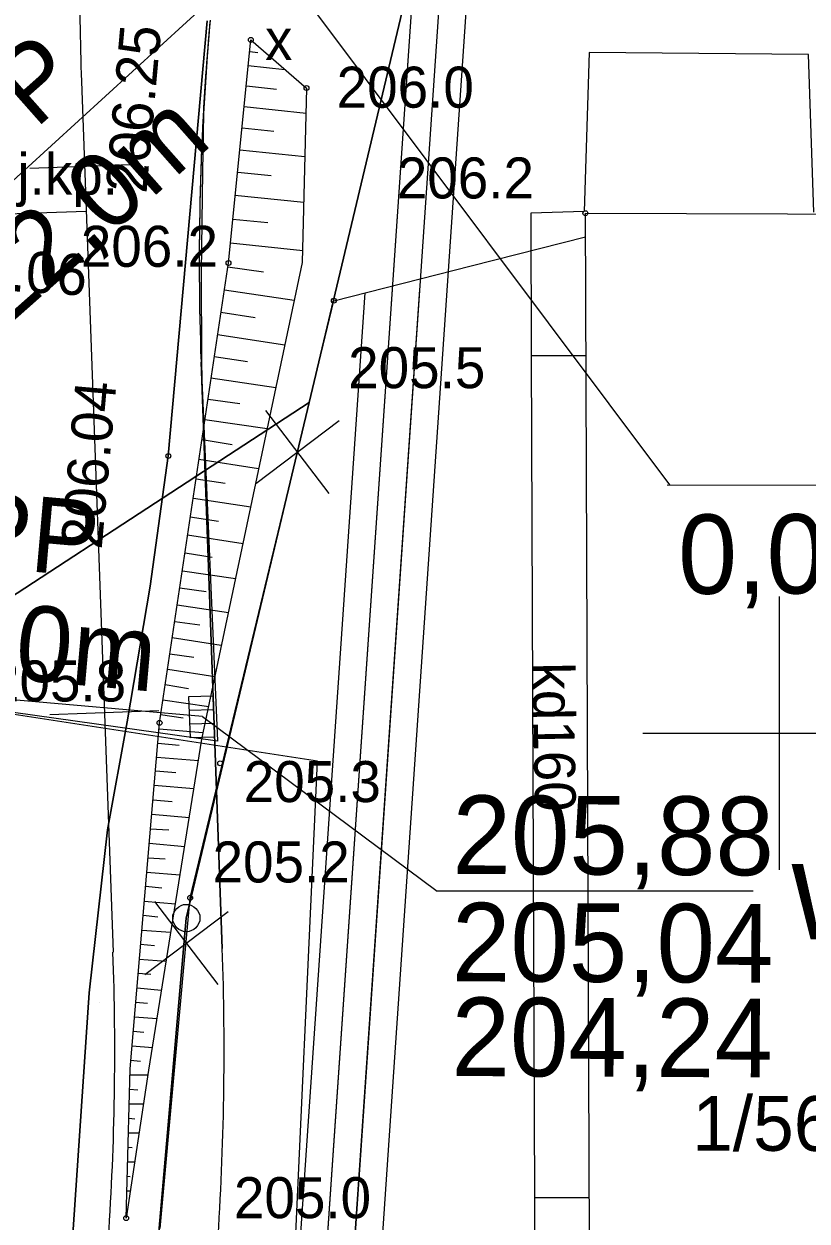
# Model space of a CAD drawing. Extents: x 6512606 to 6513347, y 6022524 to 6022728.
# Drawn here: x 6512736.18 to 6512750.51, y 6022641.08 to 6022662.97 of the extents above; entities that cross this region are included whole.
import ezdxf

# ---------------------------------------------------------------- set-up
doc = ezdxf.new("R2010")
doc.units = 0
for name, color, linetype in [('000 Inne (niezydentyfikowane)', 7, 'Continuous'), ('20', 7, 'Continuous'), ('202-punkt graniczny', 7, 'Continuous'), ('211-numer działki ewidencyjnej', 7, 'Continuous'), ('218-kontur użytku gruntowego', 7, 'Continuous'), ('219-działka ewidencyjna', 7, 'Continuous'), ('312-budynek ewidencyjny', 7, 'Continuous'), ('4', 7, 'Continuous'), ('Default', 7, 'Continuous'), ('jezdnia (powierzchnia)', 7, 'Continuous'), ('jezdnia (powierzchnia)-Atr17', 7, 'Continuous'), ('kolor_kostka_bet', 7, 'Continuous'), ('krawężnik (linia)', 7, 'Continuous'), ('Level 47', 7, 'Continuous'), ('Level 60', 7, 'Continuous'), ('maxp_kan_deszczowa', 7, 'Continuous'), ('maxp_kratki', 7, 'Continuous'), ('maxp_krawężnik', 7, 'Continuous'), ('maxp_likwidacje', 7, 'Continuous'), ('maxp_opisy', 7, 'Continuous'), ('maxp_os', 7, 'Continuous'), ('maxp_ramka_2', 7, 'Continuous'), ('ogrodzenie', 7, 'Continuous'), ('ogrodzenie trwałe (linia)', 7, 'Continuous'), ('pikieta naturalna', 7, 'Continuous'), ('pikieta naturalna-Atr2', 7, 'Continuous'), ('przewód kanalizacyjny (linia)', 7, 'Continuous'), ('przewód kanalizacyjny (linia)-Atr1', 7, 'Continuous'), ('punkt wysokościowy naturalny', 7, 'Continuous'), ('punkt wysokościowy naturalny-Atr2', 7, 'Continuous'), ('punkt wysokościowy sztuczny', 7, 'Continuous'), ('punkt wysokościowy sztuczny-Atr2', 7, 'Continuous'), ('skarpa nieumocniona', 7, 'Continuous'), ('właz okrągły - siec niezidentyfikowana (punkt)-Atr17', 7, 'Continuous')]:
    doc.layers.add(name, color=color, linetype=linetype)

# ---------------------------------------------------------------- blocks, each defined once
blk = doc.blocks.new('202')
at = {"layer": 'Default'}
blk.add_circle((0, 0), 2.5, dxfattribs=at)
blk = doc.blocks.new('PW01')
at = {"layer": 'Default'}
blk.add_circle((0, 0), 0.45, dxfattribs=at)
blk = doc.blocks.new('PW02')
at = {"layer": 'Default'}
blk.add_circle((0, 0), 0.45, dxfattribs=at)

msp = doc.modelspace()

# ---------------------------------------------------------------- linework, layer by layer
msp.add_line((6512740.034, 6022615.911), (6512743.337, 6022664.192))
msp.add_arc((6512787.452, 6022641.666), 50, 176.0863, 176.0865)
msp.add_arc((6512787.452, 6022641.666), 50, 176.0863, 176.0865)
at = {"layer": '000 Inne (niezydentyfikowane)'}
for points in [[(6512740.31, 6022662.47), (6512740.46, 6022662.45)], [(6512740.28, 6022662.21), (6512740.95, 6022662.14)], [(6512740.25, 6022661.84), (6512740.8, 6022661.78)], [(6512740.21, 6022661.46), (6512741.34, 6022661.34)], [(6512740.17, 6022661.07), (6512740.75, 6022661.01)], [(6512740.13, 6022660.67), (6512741.32, 6022660.55)], [(6512740.09, 6022660.26), (6512740.7, 6022660.2)], [(6512740.04, 6022659.84), (6512741.3, 6022659.71)], [(6512740, 6022659.4), (6512740.64, 6022659.34)], [(6512739.96, 6022658.97), (6512741.28, 6022658.83)], [(6512739.91, 6022658.53), (6512740.56, 6022658.44)], [(6512739.85, 6022658.11), (6512741.12, 6022657.92)], [(6512739.78, 6022657.7), (6512740.41, 6022657.6)], [(6512739.72, 6022657.29), (6512740.95, 6022657.1)], [(6512739.66, 6022656.89), (6512740.27, 6022656.8)], [(6512739.6, 6022656.5), (6512740.79, 6022656.32)], [(6512739.55, 6022656.11), (6512740.13, 6022656.03)], [(6512739.49, 6022655.74), (6512740.63, 6022655.57)], [(6512739.44, 6022655.37), (6512739.99, 6022655.28)], [(6512739.38, 6022655.01), (6512740.47, 6022654.84)], [(6512739.33, 6022654.65), (6512739.86, 6022654.57)], [(6512739.28, 6022654.3), (6512740.33, 6022654.14)], [(6512739.22, 6022653.96), (6512739.74, 6022653.88)], [(6512739.17, 6022653.63), (6512740.19, 6022653.47)], [(6512739.13, 6022653.3), (6512739.62, 6022653.22)], [(6512739.08, 6022652.97), (6512740.05, 6022652.83)], [(6512739.03, 6022652.66), (6512739.51, 6022652.59)], [(6512738.98, 6022652.35), (6512739.92, 6022652.21)], [(6512738.94, 6022652.04), (6512739.4, 6022651.98)], [(6512738.89, 6022651.75), (6512739.79, 6022651.61)], [(6512738.85, 6022651.45), (6512739.29, 6022651.39)], [(6512738.81, 6022651.17), (6512739.67, 6022651.04)], [(6512738.76, 6022650.89), (6512739.19, 6022650.82)], [(6512738.72, 6022650.61), (6512739.56, 6022650.49)], [(6512738.68, 6022650.34), (6512739.09, 6022650.28)], [(6512738.65, 6022650.08), (6512739.45, 6022650.01)], [(6512738.63, 6022649.82), (6512739.02, 6022649.78)], [(6512738.61, 6022649.56), (6512739.37, 6022649.5)], [(6512738.59, 6022649.31), (6512738.96, 6022649.28)], [(6512738.56, 6022649.05), (6512739.29, 6022648.99)], [(6512738.54, 6022648.78), (6512738.89, 6022648.75)], [(6512738.52, 6022648.52), (6512739.2, 6022648.46)], [(6512738.49, 6022648.25), (6512738.83, 6022648.23)], [(6512738.47, 6022647.99), (6512739.12, 6022647.93)], [(6512738.45, 6022647.72), (6512738.76, 6022647.7)], [(6512738.43, 6022647.46), (6512739.03, 6022647.41)], [(6512738.4, 6022647.2), (6512738.7, 6022647.17)], [(6512738.38, 6022646.93), (6512738.95, 6022646.88)], [(6512738.36, 6022646.67), (6512738.63, 6022646.64)], [(6512738.34, 6022646.4), (6512738.86, 6022646.36)], [(6512738.31, 6022646.14), (6512738.57, 6022646.12)], [(6512738.29, 6022645.87), (6512738.78, 6022645.83)], [(6512738.27, 6022645.61), (6512738.5, 6022645.59)], [(6512738.25, 6022645.34), (6512738.69, 6022645.3)], [(6512738.22, 6022645.08), (6512738.44, 6022645.06)], [(6512738.2, 6022644.81), (6512738.61, 6022644.78)], [(6512738.18, 6022644.55), (6512738.37, 6022644.53)], [(6512738.16, 6022644.28), (6512738.53, 6022644.25)], [(6512738.13, 6022644.02), (6512738.31, 6022644)], [(6512738.12, 6022643.75), (6512738.45, 6022643.75)], [(6512738.11, 6022643.49), (6512738.26, 6022643.48)], [(6512738.1, 6022643.22), (6512738.37, 6022643.22)], [(6512738.1, 6022642.96), (6512738.21, 6022642.95)], [(6512738.09, 6022642.69), (6512738.29, 6022642.69)], [(6512738.08, 6022642.43), (6512738.16, 6022642.42)], [(6512738.08, 6022642.16), (6512738.21, 6022642.16)], [(6512738.07, 6022641.9), (6512738.12, 6022641.89)], [(6512738.06, 6022641.63), (6512738.13, 6022641.63)]]:
    msp.add_lwpolyline(points, dxfattribs=at)
at = {"layer": '20'}
for p in [(6512739.443, 6022650.303), (6512749.517, 6022647.111)]:
    msp.add_line(p, (6512743.737, 6022647.111), dxfattribs=at)
at = {"layer": '218-kontur użytku gruntowego'}
for points in [[(6512745.51, 6022673.33), (6512741.4, 6022656.05)], [(6512741.4, 6022656.05), (6512745.51, 6022673.33)], [(6512741.4, 6022656.05), (6512733.08, 6022650.62)], [(6512733.08, 6022650.62), (6512741.4, 6022656.05)], [(6512741.4, 6022656.05), (6512739.15, 6022646.62)], [(6512739.15, 6022646.62), (6512741.4, 6022656.05)], [(6512739.15, 6022646.62), (6512737.73, 6022630.38)], [(6512737.73, 6022630.38), (6512739.15, 6022646.62)]]:
    msp.add_lwpolyline(points, dxfattribs=at)
at = {"layer": '219-działka ewidencyjna'}
for points in [[(6512745.51, 6022673.33), (6512739.15, 6022646.62)], [(6512739.15, 6022646.62), (6512735.75, 6022607.64)]]:
    msp.add_lwpolyline(points, dxfattribs=at)
at = {"layer": '312-budynek ewidencyjny'}
for points in [[(6512746.45, 6022659.51), (6512759.38, 6022659.47)], [(6512746.53, 6022639.13), (6512746.45, 6022659.51)]]:
    msp.add_lwpolyline(points, dxfattribs=at)
at = {"layer": '4'}
for points in [[(6512745.51, 6022673.33), (6512739.15, 6022646.62)], [(6512739.15, 6022646.62), (6512735.75, 6022607.64)]]:
    msp.add_lwpolyline(points, dxfattribs=at)
at = {"layer": 'Default'}
for p, q in [((6512750, 6022647.5), (6512750, 6022652.5)), ((6512747.5, 6022650), (6512752.5, 6022650))]:
    msp.add_line(p, q, dxfattribs=at)
at = {"layer": 'jezdnia (powierzchnia)'}
msp.add_lwpolyline([(6512736.3, 6022629.38), (6512737.37, 6022645.25), (6512737.71, 6022648.23), (6512738.07, 6022650.21), (6512738.49, 6022652.69), (6512738.82, 6022655.07), (6512739.53, 6022663.03)], dxfattribs=at)
at = {"layer": 'kolor_kostka_bet'}
for p, q in [((6512740.868, 6022628.114), (6512743.337, 6022664.192)), ((6512739.807, 6022646.065), (6512739.419, 6022656.788)), ((6512739.419, 6022656.788), (6512739.807, 6022646.065))]:
    msp.add_line(p, q, dxfattribs=at)
for centre, radius, start, end in [((6512789.386, 6022658.599), 50, 174.9005, 182.076), ((6512789.386, 6022658.599), 50, 174.9607, 182.076), ((6512687.841, 6022644.182), 52, 356.0865, 2.076), ((6512687.841, 6022644.182), 52, 356.0868, 2.076)]:
    msp.add_arc(centre, radius, start, end, dxfattribs=at)
at = {"layer": 'krawężnik (linia)'}
msp.add_lwpolyline([(6512739.53, 6022663.03), (6512738.82, 6022655.07), (6512738.49, 6022652.69), (6512738.07, 6022650.21), (6512737.71, 6022648.23), (6512737.37, 6022645.25), (6512736.3, 6022629.38)], dxfattribs=at)
at = {"layer": 'Level 60'}
for points in [[(6512738.287, 6022660.401), (6512736.288, 6022660.329)], [(6512738.649, 6022650.408), (6512736.651, 6022650.336)]]:
    msp.add_lwpolyline(points, dxfattribs=at)
at = {"layer": 'maxp_kan_deszczowa'}
for p, q in [((6512742.335, 6022665.911), (6512733.933, 6022658.237)), ((6512739.443, 6022650.303), (6512726.489, 6022651.44))]:
    msp.add_line(p, q, dxfattribs=at)
for points in [[(6512739.581, 6022663.017), (6512739.565, 6022662.833), (6512739.529, 6022662.375), (6512739.461, 6022661.334), (6512739.447, 6022660.268), (6512739.419, 6022658.432), (6512739.425, 6022656.82), (6512739.431, 6022656.459), (6512739.721, 6022649.859), (6512739.722, 6022649.854), (6512735.636, 6022650.43), (6512730.761, 6022651.18), (6512730.761, 6022651.18), (6512730.281, 6022651.648), (6512729.689, 6022652.24), (6512729.197, 6022652.769), (6512729.197, 6022652.769), (6512729.196, 6022652.768), (6512728.623, 6022653.883), (6512728.624, 6022653.883), (6512727.858, 6022655.465), (6512725.644, 6022659.663), (6512728.487, 6022663.067)], [(6512741.065, 6022638.988), (6512741.55, 6022649.49), (6512730.76, 6022651.147), (6512730.76, 6022651.147), (6512730.665, 6022649.115), (6512730.652, 6022648.777), (6512730.588, 6022647.474), (6512730.511, 6022645.827), (6512730.451, 6022644.413), (6512730.397, 6022643.379), (6512730.27, 6022641.07)]]:
    msp.add_lwpolyline(points, dxfattribs=at)
at = {"layer": 'maxp_kratki'}
for p, q in [((6512739.64, 6022650.679), (6512739.19, 6022650.663)), ((6512739.19, 6022650.663), (6512739.218, 6022649.914)), ((6512739.64, 6022650.679), (6512739.667, 6022649.93)), ((6512739.649, 6022650.429), (6512739.2, 6022650.414)), ((6512739.658, 6022650.18), (6512739.208, 6022650.164)), ((6512739.667, 6022649.93), (6512739.218, 6022649.914))]:
    msp.add_line(p, q, dxfattribs=at)
at = {"layer": 'maxp_krawężnik'}
msp.add_line((6512739.419, 6022656.788), (6512739.807, 6022646.065), dxfattribs=at)
for centre, radius, start, end in [((6512789.386, 6022658.599), 50, 174.9005, 182.076), ((6512687.841, 6022644.182), 52, 356.0865, 2.076)]:
    msp.add_arc(centre, radius, start, end, dxfattribs=at)
at = {"layer": 'maxp_likwidacje'}
for p, q in [((6512741.761, 6022654.383), (6512740.606, 6022655.903)), ((6512740.424, 6022654.566), (6512741.944, 6022655.721)), ((6512739.731, 6022645.402), (6512738.575, 6022646.922)), ((6512738.393, 6022645.584), (6512739.913, 6022646.739))]:
    msp.add_line(p, q, dxfattribs=at)
at = {"layer": 'maxp_opisy'}
for p, q in [((6512739.811, 6022665.462), (6512747.991, 6022654.543)), ((6512747.949, 6022654.543), (6512755.861, 6022654.532))]:
    msp.add_line(p, q, dxfattribs=at)
at = {"layer": 'maxp_os'}
for p, q in [((6512737.231, 6022661.918), (6512737.809, 6022645.993)), ((6512731.809, 6022659.351), (6512737.317, 6022659.55))]:
    msp.add_line(p, q, dxfattribs=at)
for centre, start, end in [((6512787.199, 6022663.73), 179.5356, 182.0758), ((6512687.841, 6022644.182), 356.0868, 2.076)]:
    msp.add_arc(centre, 50, start, end, dxfattribs=at)
at = {"layer": 'maxp_ramka_2'}
for p, q in [((6512740.266, 6022611.979), (6512743.834, 6022664.131)), ((6512740.778, 6022612.146), (6512744.33, 6022664.055)), ((6512740.266, 6022611.979), (6512743.422, 6022658.115)), ((6512740.266, 6022611.979), (6512743.422, 6022658.115))]:
    msp.add_line(p, q, dxfattribs=at)
at = {"layer": 'ogrodzenie'}
msp.add_line((6512742.416, 6022658.054), (6512740.388, 6022628.41), dxfattribs=at)
at = {"layer": 'ogrodzenie trwałe (linia)'}
msp.add_lwpolyline([(6512738.67, 6022640.94), (6512739.22, 6022646.99), (6512741.85, 6022657.91), (6512744.36, 6022658.55), (6512746.45, 6022659.08)], dxfattribs=at)
at = {"layer": 'przewód kanalizacyjny (linia)'}
for points in [[(6512750.63, 6022659.53), (6512750.53, 6022662.41), (6512746.52, 6022662.45), (6512746.43, 6022659.54), (6512745.45, 6022659.51), (6512745.46, 6022656.91), (6512745.52, 6022641.51), (6512745.53, 6022639.13), (6512748.39, 6022633.94), (6512759.09, 6022633.91), (6512760.48, 6022633.91), (6512760.44, 6022639.05)], [(6512745.46, 6022656.91), (6512746.45, 6022656.91)], [(6512745.52, 6022641.51), (6512746.52, 6022641.51)]]:
    msp.add_lwpolyline(points, dxfattribs=at)
at = {"layer": 'skarpa nieumocniona'}
msp.add_lwpolyline([(6512738.05, 6022641.13), (6512738.12, 6022643.86), (6512738.66, 6022650.19), (6512739.92, 6022658.6), (6512740.33, 6022662.68), (6512741.35, 6022661.8), (6512741.27, 6022658.61), (6512739.43, 6022649.89), (6512738.46, 6022643.84)], close=True, dxfattribs=at)
msp.add_lwpolyline([(6512738.05, 6022641.13), (6512738.12, 6022643.86), (6512738.66, 6022650.19), (6512739.92, 6022658.6), (6512740.33, 6022662.68), (6512741.35, 6022661.8), (6512741.27, 6022658.61), (6512739.43, 6022649.89), (6512738.46, 6022643.84)], close=True, dxfattribs=at)

# ---------------------------------------------------------------- block references
at = {"layer": '202-punkt graniczny', "xscale": 0.1, "yscale": 0.10000000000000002}
msp.add_blockref('202', (6512739.15, 6022646.62), dxfattribs=at)
at = {"layer": 'pikieta naturalna', "xscale": 0.1, "yscale": 0.10000000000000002}
for p in [(6512740.33, 6022662.68), (6512741.35, 6022661.8), (6512739.92, 6022658.6), (6512738.66, 6022650.19), (6512739.77, 6022649.45), (6512738.05, 6022641.13)]:
    msp.add_blockref('PW01', p, dxfattribs=at)
at = {"layer": 'punkt wysokościowy naturalny', "xscale": 0.1, "yscale": 0.10000000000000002}
for p in [(6512746.45, 6022659.51), (6512741.85, 6022657.91), (6512739.22, 6022646.99)]:
    msp.add_blockref('PW01', p, dxfattribs=at)
at = {"layer": 'punkt wysokościowy sztuczny', "xscale": 0.1, "yscale": 0.10000000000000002}
msp.add_blockref('PW02', (6512738.82, 6022655.07), dxfattribs=at)

# ---------------------------------------------------------------- texts
at = {"layer": '211-numer działki ewidencyjnej'}
msp.add_text('1/56', height=1, dxfattribs=at).set_placement((6512748.403, 6022642.362))
at = {"layer": 'jezdnia (powierzchnia)-Atr17'}
msp.add_text('j.kp.', height=0.75, dxfattribs=at).set_placement((6512736.06, 6022659.85))
at = {"layer": 'Level 47'}
for s, height, rotation, p in [('315 PP', 1.3824, 41.5157, (6512732.771, 6022657.837)), ('L=22,0m', 1.3824, 41.5157, (6512734.229, 6022655.98)), ('160 PP', 1.3824, 354.9696, (6512731.449, 6022653.385)), ('L=13,0m', 1.3824, 354.9696, (6512731.325, 6022651.395)), ('205,88', 1.4377, 359.7281, (6512744.016, 6022647.427)), ('wp1', 1.7971, 359.7281, (6512750.219, 6022646.23)), ('205,04', 1.4377, 359.7281, (6512744.006, 6022645.463)), ('204,24', 1.4377, 359.7281, (6512743.998, 6022643.731))]:
    msp.add_text(s, height=height, rotation=rotation, dxfattribs=at).set_placement(p)
at = {"layer": 'maxp_opisy'}
msp.add_text('0,0322[ha]', height=1.4515, rotation=0.1859, dxfattribs=at).set_placement((6512748.148, 6022652.547))
at = {"layer": 'pikieta naturalna-Atr2'}
for s, p in [('206.0', (6512741.9, 6022661.44)), ('206.2', (6512737.22, 6022658.53)), ('205.8', (6512735.54, 6022650.58)), ('205.3', (6512740.2, 6022648.74)), ('205.0', (6512740.02, 6022641.13))]:
    msp.add_text(s, height=0.75, dxfattribs=at).set_placement(p)
at = {"layer": 'przewód kanalizacyjny (linia)-Atr1'}
msp.add_text('kd160', height=0.75, rotation=271.005, dxfattribs=at).set_placement((6512745.48, 6022651.29))
at = {"layer": 'punkt wysokościowy naturalny-Atr2'}
for s, p in [('206.2', (6512743, 6022659.78)), ('205.5', (6512742.11, 6022656.31)), ('205.2', (6512739.63, 6022647.27))]:
    msp.add_text(s, height=0.75, dxfattribs=at).set_placement(p)
at = {"layer": 'punkt wysokościowy sztuczny-Atr2'}
for s, rotation, p in [('206.25', 84.903, (6512738.42, 6022659.86)), ('206.06', 356.458, (6512734.25, 6022658.19)), ('206.04', 84.903, (6512737.6, 6022653.35))]:
    msp.add_text(s, height=0.75, rotation=rotation, dxfattribs=at).set_placement(p)
at = {"layer": 'właz okrągły - siec niezidentyfikowana (punkt)-Atr17'}
msp.add_text('x', height=0.75, dxfattribs=at).set_placement((6512740.59, 6022662.31))

doc.saveas('drawing.dxf')
